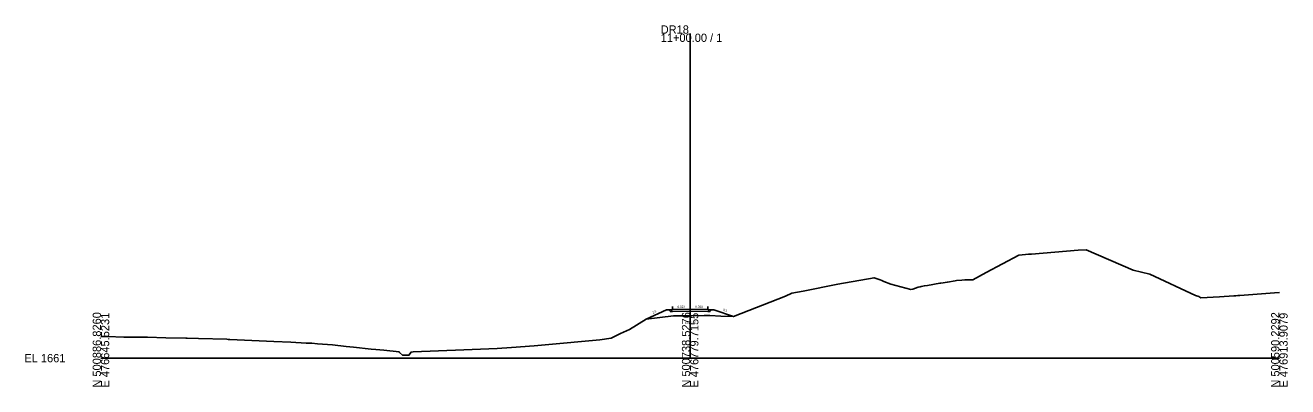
# Model space of a CAD drawing. Extents: x -26 to 403, y -10 to 2113.
# Drawn here: x -25.7 to 402.8, y 1990.3 to 2112.9 of the extents above; entities that cross this region are included whole.
import ezdxf

# ---------------------------------------------------------------- set-up
doc = ezdxf.new("R2010")
doc.units = 0
for name, color, linetype in [('Exist Cross Section Cell', 7, 'Continuous'), ('Exist XS Center Line Elevation Label', 7, 'Continuous'), ('Exist XS Ground Line', 7, 'Continuous'), ('Prop XS Earthwork Shape', 7, 'Continuous'), ('Prop XS EOT Tick Mark', 7, 'Continuous'), ('Prop XS Finish Grade', 7, 'Continuous'), ('Prop XS Finish Grade Earthwork', 7, 'Continuous'), ('Prop XS Finish Grade Pavement', 7, 'Continuous'), ('Prop XS Pvmt Edge Slope', 7, 'Continuous'), ('Prop XS SE Text', 7, 'Continuous'), ('Prop XS Shoulder Borrow Shape', 7, 'Continuous'), ('Prop XS Side Slope Text', 7, 'Continuous'), ('Prop XS Subgrade Earthwork', 7, 'Continuous')]:
    doc.layers.add(name, color=color, linetype=linetype)

msp = doc.modelspace()

# ---------------------------------------------------------------- linework, layer by layer
at = {"layer": 'Exist Cross Section Cell'}
for p, q in [((200, 2000), (200, 2110.07)), ((0, 2000), (200, 2000)), ((200, 2000), (400, 2000))]:
    msp.add_line(p, q, dxfattribs=at)
at = {"layer": 'Exist XS Ground Line'}
msp.add_lwpolyline([(0, 2007.36), (0.73, 2007.36), (2.27, 2007.31), (7.81, 2007.17), (13.94, 2007.13), (14.89, 2007.12), (15.75, 2007.11), (21.97, 2006.95), (28.84, 2006.82), (29.24, 2006.8), (33.06, 2006.69), (42.73, 2006.39), (43.22, 2006.38), (43.75, 2006.36), (56.22, 2005.74), (58.66, 2005.67), (64.46, 2005.47), (69.71, 2005.13), (71.54, 2005.03), (73.56, 2004.89), (78.62, 2004.52), (83.2, 2003.95), (85.7, 2003.68), (91.69, 2003.09), (93.36, 2002.93), (96, 2002.68), (101.21, 2002.2), (101.34, 2001.88), (102.34, 2001.05), (104.01, 2000.99), (104.56, 2000.97), (105.27, 2002.06), (105.98, 2002.19), (123.13, 2002.79), (134.53, 2003.31), (139.4, 2003.63), (147, 2004.2), (150.83, 2004.51), (169.36, 2006.24), (173.16, 2006.75), (176.41, 2008.37), (179.38, 2009.74), (185.05, 2013.25), (194.38, 2014.35), (200, 2014.35), (200.54, 2014.35), (204.73, 2014.52), (205.25, 2014.51), (206.31, 2014.49), (206.68, 2014.45), (210.38, 2014.29), (214.67, 2014.18), (232.39, 2021.05), (234.46, 2021.99), (238.39, 2022.76), (250.07, 2025.05), (262.42, 2027.3), (264.48, 2026.52), (265.1, 2026.29), (265.79, 2026.03), (268.14, 2025.14), (274.89, 2023.25), (275.57, 2023.45), (277.42, 2024.09), (278.06, 2024.23), (278.4, 2024.28), (279.52, 2024.54), (280.51, 2024.63), (284.74, 2025.43), (285.09, 2025.46), (287.3, 2025.83), (290, 2026.25), (290.45, 2026.32), (292.17, 2026.51), (293.18, 2026.62), (295.32, 2026.59), (295.92, 2026.58), (300.49, 2029.01), (311.53, 2034.9), (313.78, 2035.12), (314.88, 2035.22), (315.91, 2035.3), (331.67, 2036.61), (334.38, 2036.69), (350.4, 2029.9), (356.06, 2028.51), (371.58, 2021.28), (372.61, 2020.88), (373.38, 2020.48), (379.69, 2020.83), (384.59, 2021.1), (385.17, 2021.15), (385.94, 2021.22), (386.62, 2021.27), (398.3, 2022.11), (400, 2022.24)], dxfattribs=at)
at = {"layer": 'Prop XS Earthwork Shape'}
msp.add_lwpolyline([(206, 2015.83), (206.68, 2015.82), (207.26, 2016.4), (208, 2016.34), (214.67, 2014.18), (210.38, 2014.29), (206.68, 2014.45), (206.31, 2014.49), (205.25, 2014.51), (204.73, 2014.52), (200.54, 2014.35), (200, 2014.35), (194.38, 2014.35), (185.05, 2013.25), (192, 2016.34), (192.74, 2016.4), (193.32, 2015.82), (194, 2015.83), (200, 2015.95)], close=True, dxfattribs=at)
at = {"layer": 'Prop XS EOT Tick Mark'}
for p, q in [((194, 2016.5), (194, 2017.5)), ((206, 2016.5), (206, 2017.5))]:
    msp.add_line(p, q, dxfattribs=at)
at = {"layer": 'Prop XS Finish Grade'}
for p, q in [((194, 2016.5), (192.74, 2016.4)), ((206, 2016.5), (207.26, 2016.4))]:
    msp.add_line(p, q, dxfattribs=at)
at = {"layer": 'Prop XS Finish Grade Earthwork'}
for p, q in [((192, 2016.34), (185.05, 2013.25)), ((192.74, 2016.4), (192, 2016.34)), ((207.26, 2016.4), (208, 2016.34)), ((208, 2016.34), (214.67, 2014.18))]:
    msp.add_line(p, q, dxfattribs=at)
at = {"layer": 'Prop XS Finish Grade Pavement'}
for p, q in [((194, 2016.5), (200, 2016.62)), ((200, 2016.62), (206, 2016.5))]:
    msp.add_line(p, q, dxfattribs=at)
at = {"layer": 'Prop XS Pvmt Edge Slope'}
for p, q in [((194, 2016.5), (193.32, 2015.82)), ((206, 2016.5), (206.68, 2015.82))]:
    msp.add_line(p, q, dxfattribs=at)
at = {"layer": 'Prop XS Shoulder Borrow Shape'}
for points in [[(193.32, 2015.82), (192.74, 2016.4), (194, 2016.5)], [(206, 2016.5), (207.26, 2016.4), (206.68, 2015.82)]]:
    msp.add_lwpolyline(points, close=True, dxfattribs=at)
at = {"layer": 'Prop XS Subgrade Earthwork'}
for p, q in [((193.32, 2015.82), (192.74, 2016.4)), ((194, 2015.83), (193.32, 2015.82)), ((200, 2015.95), (194, 2015.83)), ((206, 2015.83), (200, 2015.95)), ((206, 2015.83), (206.68, 2015.82)), ((206.68, 2015.82), (207.26, 2016.4))]:
    msp.add_line(p, q, dxfattribs=at)

# ---------------------------------------------------------------- texts
at = {"layer": 'Exist Cross Section Cell'}
for s, p in [('DR18', (190, 2110.07)), ('11+00.00 / 1', (190, 2107.27)), ('EL 1661', (-26, 1998.6))]:
    msp.add_text(s, height=2.8, dxfattribs=at).set_placement(p)
for s, p in [('N 500886.8260', (0, 1990)), ('E 476645.5231', (2.8, 1990)), ('N 500738.5276', (200, 1990)), ('E 476779.7155', (202.8, 1990)), ('N 500590.2292', (400, 1990)), ('E 476913.9079', (402.8, 1990))]:
    msp.add_text(s, height=2.8, rotation=90, dxfattribs=at).set_placement(p)
at = {"layer": 'Exist XS Center Line Elevation Label'}
msp.add_text('1675.35', height=0.75, dxfattribs=at).set_placement((198.23, 2011.6))
at = {"layer": 'Prop XS SE Text'}
for rotation, p in [(1.1458, (195.69, 2017.03)), (358.8542, (201.69, 2017.09))]:
    msp.add_text('0.020', height=0.75, rotation=rotation, dxfattribs=at).set_placement(p)
at = {"layer": 'Prop XS Side Slope Text'}
for s, rotation, p in [('2:1', 26.5651, (187.36, 2015.05)), ('3:1', 342.0731, (211.05, 2016.1))]:
    msp.add_text(s, height=0.75, rotation=rotation, dxfattribs=at).set_placement(p)

doc.saveas('drawing.dxf')
